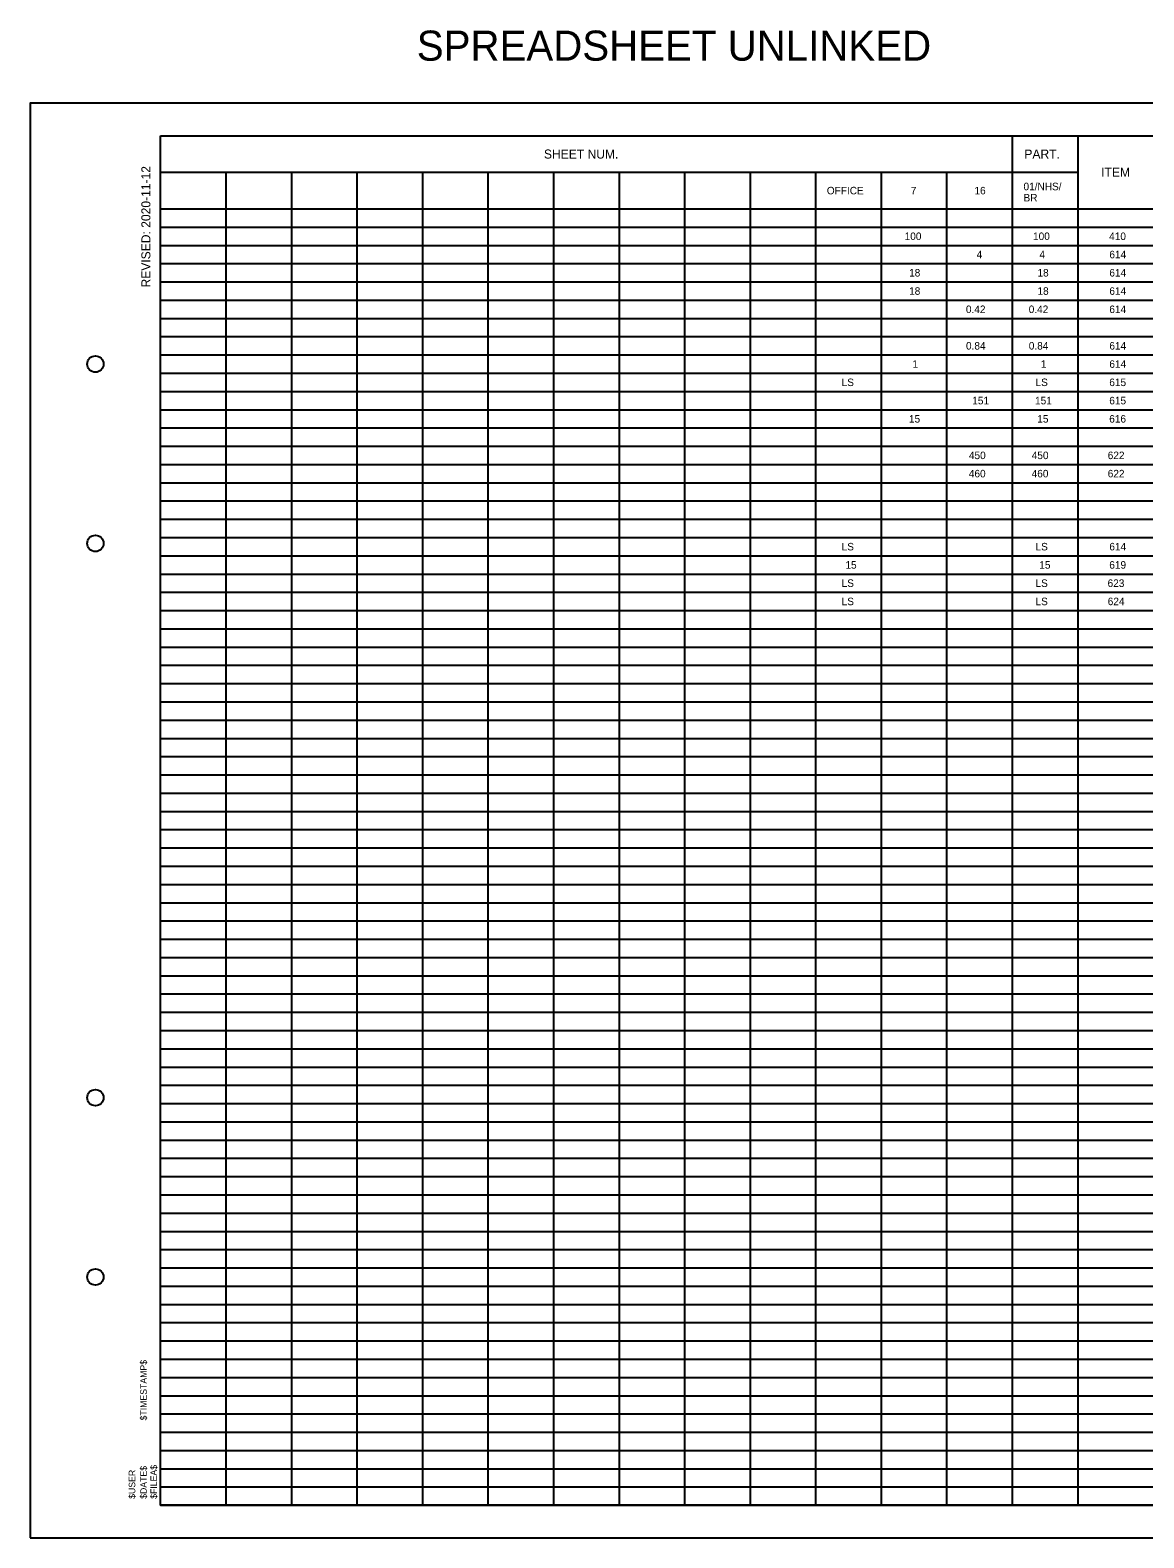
# Model space of a CAD drawing. Extents: x 0 to 34, y 0 to 23.1.
# Drawn here: x 0 to 17.07, y 0 to 23.12 of the extents above; entities that cross this region are included whole.
import ezdxf

# ---------------------------------------------------------------- set-up
doc = ezdxf.new("R2010")
doc.units = 0
for name, color, linetype in [('SH_Border', 7, 'Continuous'), ('SH_Cut_Line', 7, 'Continuous'), ('SH_Data', 7, 'Continuous'), ('SH_Text', 7, 'Continuous')]:
    doc.layers.add(name, color=color, linetype=linetype)

msp = doc.modelspace()

# ---------------------------------------------------------------- linework, layer by layer
at = {"layer": 'SH_Border'}
msp.add_lwpolyline([(2, 21.5), (33.5, 21.5), (33.5, 0.5), (2, 0.5)], close=True, dxfattribs=at)
for centre in [(1, 18), (1, 15.25), (1, 6.75), (1, 4)]:
    msp.add_circle(centre, 0.125, dxfattribs=at)
at = {"layer": 'SH_Cut_Line'}
msp.add_lwpolyline([(0, 0), (34, 0), (34, 22), (0, 22)], close=True, dxfattribs=at)
at = {"layer": 'SH_Text'}
for p, q in [((2, 21.5), (2, 21.5)), ((2, 21.5), (32.5, 21.5)), ((2, 0.5), (2, 21.5)), ((15.06, 0.5), (15.06, 21.5)), ((16.064, 0.5), (16.064, 21.5)), ((2, 20.94), (16.064, 20.94)), ((3.005, 0.5), (3.005, 20.94)), ((4.009, 0.5), (4.009, 20.94)), ((5.014, 0.5), (5.014, 20.94)), ((6.018, 0.5), (6.018, 20.94)), ((7.023, 0.5), (7.023, 20.94)), ((8.028, 0.5), (8.028, 20.94)), ((9.032, 0.5), (9.032, 20.94)), ((10.037, 0.5), (10.037, 20.94)), ((11.041, 0.5), (11.041, 20.94)), ((12.046, 0.5), (12.046, 20.94)), ((13.05, 0.5), (13.05, 20.94)), ((14.055, 0.5), (14.055, 20.94)), ((2, 20.38), (15.06, 20.38)), ((14.055, 20.38), (32.5, 20.38)), ((2, 20.1), (32.5, 20.1)), ((2, 19.82), (32.5, 19.82)), ((2, 19.54), (32.5, 19.54)), ((2, 19.26), (32.5, 19.26)), ((2, 18.98), (32.5, 18.98)), ((2, 18.7), (32.5, 18.7)), ((2, 18.42), (32.5, 18.42)), ((2, 18.14), (32.5, 18.14)), ((2, 17.86), (32.5, 17.86)), ((2, 17.58), (32.5, 17.58)), ((2, 17.3), (32.5, 17.3)), ((2, 17.02), (32.5, 17.02)), ((2, 16.74), (32.5, 16.74)), ((2, 16.46), (32.5, 16.46)), ((2, 16.18), (32.5, 16.18)), ((2, 15.9), (32.5, 15.9)), ((2, 15.62), (32.5, 15.62)), ((2, 15.34), (32.5, 15.34)), ((2, 15.06), (32.5, 15.06)), ((2, 14.78), (32.5, 14.78)), ((2, 14.5), (32.5, 14.5)), ((2, 14.22), (32.5, 14.22)), ((2, 13.94), (32.5, 13.94)), ((2, 13.66), (32.5, 13.66)), ((2, 13.38), (32.5, 13.38)), ((2, 13.1), (32.5, 13.1)), ((2, 12.82), (32.5, 12.82)), ((2, 12.54), (32.5, 12.54)), ((2, 12.26), (32.5, 12.26)), ((2, 11.98), (32.5, 11.98)), ((2, 11.7), (32.5, 11.7)), ((2, 11.42), (32.5, 11.42)), ((2, 11.14), (32.5, 11.14)), ((2, 10.86), (32.5, 10.86)), ((2, 10.58), (32.5, 10.58)), ((2, 10.3), (32.5, 10.3)), ((2, 10.02), (32.5, 10.02)), ((2, 9.74), (32.5, 9.74)), ((2, 9.46), (32.5, 9.46)), ((2, 9.18), (32.5, 9.18)), ((2, 8.9), (32.5, 8.9)), ((2, 8.62), (32.5, 8.62)), ((2, 8.34), (32.5, 8.34)), ((2, 8.06), (32.5, 8.06)), ((2, 7.78), (32.5, 7.78)), ((2, 7.5), (32.5, 7.5)), ((2, 7.22), (32.5, 7.22)), ((2, 6.94), (32.5, 6.94)), ((2, 6.66), (32.5, 6.66)), ((2, 6.38), (32.5, 6.38)), ((2, 6.1), (32.5, 6.1)), ((2, 5.82), (32.5, 5.82)), ((2, 5.54), (32.5, 5.54)), ((2, 5.26), (32.5, 5.26)), ((2, 4.98), (32.5, 4.98)), ((2, 4.7), (32.5, 4.7)), ((2, 4.42), (32.5, 4.42)), ((2, 4.14), (32.5, 4.14)), ((2, 3.86), (32.5, 3.86)), ((2, 3.58), (32.5, 3.58)), ((2, 3.3), (32.5, 3.3)), ((2, 3.02), (32.5, 3.02)), ((2, 2.74), (32.5, 2.74)), ((2, 2.46), (32.5, 2.46)), ((2, 2.18), (32.5, 2.18)), ((2, 1.9), (32.5, 1.9)), ((2, 1.62), (32.5, 1.62)), ((2, 1.34), (32.5, 1.34)), ((2, 1.06), (32.5, 1.06)), ((2, 0.78), (32.5, 0.78)), ((2, 0.5), (32.5, 0.5))]:
    msp.add_line(p, q, dxfattribs=at)

# ---------------------------------------------------------------- texts
at = {"layer": 'SH_Data'}
for s, p in [('$TIMESTAMP$', (1.788, 1.8)), ('$USER', (1.611, 0.598)), ('$DATE$', (1.788, 0.598)), ('$FILEA$', (1.944, 0.598))]:
    msp.add_text(s, height=0.1, rotation=89.9931, dxfattribs=at).set_placement(p)
at = {"layer": 'SH_Text'}
for s, height, p in [('SPREADSHEET UNLINKED ', 0.46136, (5.927, 22.652)), ('SHEET NUM.', 0.1384, (7.876, 21.151)), ('PART.', 0.1384, (15.241, 21.151)), ('ITEM', 0.1384, (16.419, 20.871)), ('OFFICE', 0.1153, (12.213, 20.602)), ('7', 0.115, (13.5, 20.602)), ('16', 0.1153, (14.476, 20.602)), ('01/NHS/', 0.1153, (15.228, 20.665)), ('BR', 0.1153, (15.228, 20.493)), ('100', 0.1153, (13.406, 19.902)), ('100', 0.1153, (15.374, 19.902)), ('410', 0.1153, (16.541, 19.902)), ('4', 0.115, (14.509, 19.622)), ('4', 0.115, (15.472, 19.622)), ('614', 0.1153, (16.544, 19.622)), ('614', 0.1153, (16.544, 19.622)), ('18', 0.1153, (13.474, 19.342)), ('18', 0.1153, (15.442, 19.342)), ('614', 0.1153, (16.544, 19.342)), ('18', 0.1153, (13.474, 19.062)), ('18', 0.1153, (15.442, 19.062)), ('614', 0.1153, (16.544, 19.062)), ('0.42', 0.1153, (14.345, 18.782)), ('0.42', 0.1153, (15.308, 18.782)), ('614', 0.1153, (16.544, 18.782)), ('0.84', 0.1153, (14.346, 18.222)), ('0.84', 0.1153, (15.309, 18.222)), ('614', 0.1153, (16.544, 18.222)), ('1', 0.115, (13.525, 17.942)), ('1', 0.115, (15.493, 17.942)), ('614', 0.1153, (16.544, 17.942)), ('LS', 0.1153, (12.44, 17.662)), ('LS', 0.1153, (15.412, 17.662)), ('615', 0.1153, (16.543, 17.662)), ('151', 0.1153, (14.442, 17.382)), ('151', 0.1153, (15.405, 17.382)), ('615', 0.1153, (16.543, 17.382)), ('15', 0.1153, (13.472, 17.102)), ('15', 0.1153, (15.439, 17.102)), ('616', 0.1153, (16.542, 17.102)), ('450', 0.1153, (14.391, 16.542)), ('450', 0.1153, (15.354, 16.542)), ('622', 0.1153, (16.519, 16.542)), ('460', 0.1153, (14.39, 16.262)), ('460', 0.1153, (15.353, 16.262)), ('622', 0.1153, (16.519, 16.262)), ('LS', 0.1153, (12.44, 15.142)), ('LS', 0.1153, (15.412, 15.142)), ('614', 0.1153, (16.544, 15.142)), ('15', 0.1153, (12.498, 14.862)), ('15', 0.1153, (12.498, 14.862)), ('15', 0.1153, (15.47, 14.862)), ('15', 0.1153, (15.47, 14.862)), ('619', 0.1153, (16.543, 14.862)), ('LS', 0.1153, (12.44, 14.582)), ('LS', 0.1153, (15.412, 14.582)), ('623', 0.1153, (16.517, 14.582)), ('LS', 0.1153, (12.44, 14.302)), ('LS', 0.1153, (15.412, 14.302)), ('624', 0.1153, (16.519, 14.302))]:
    msp.add_text(s, height=height, dxfattribs=at).set_placement(p)
msp.add_text('REVISED: 2020-11-12', height=0.13841, rotation=90, dxfattribs=at).set_placement((1.843, 19.174))

doc.saveas('drawing.dxf')
